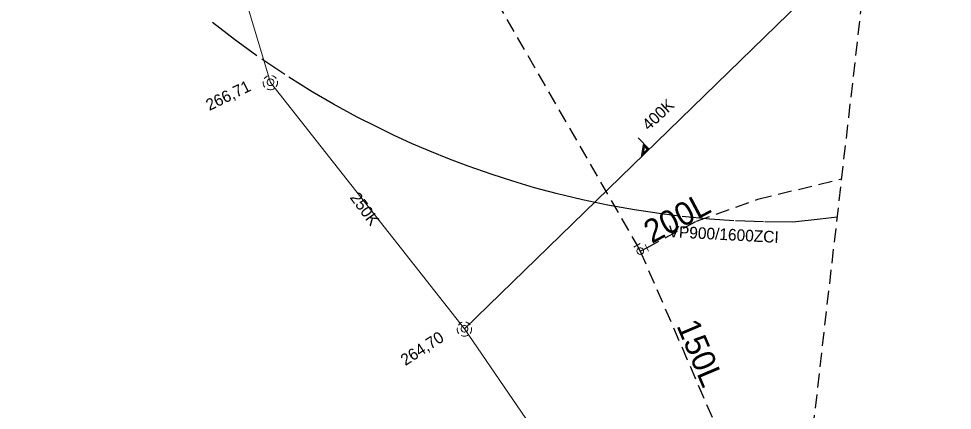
# Model space of a CAD drawing. Extents: x -743212 to -743020, y -1051380 to -1051228.
# Drawn here: x -743084.5 to -743020, y -1051325.4 to -1051298.4 of the extents above; entities that cross this region are included whole.
import ezdxf

# ---------------------------------------------------------------- set-up
doc = ezdxf.new("R2010")
doc.units = 0
doc.header["$LTSCALE"] = 0.32
doc.linetypes.add('LONG_DASHED', pattern=[7.5, 6, -1.5])
doc.linetypes.add('MEDIUM_DASHED', pattern=[4.5, 3, -1.5])
for name, color, linetype, lineweight in [('1', 7, 'MEDIUM_DASHED', 25), ('18', 7, 'Continuous', 13), ('20', 7, 'Continuous', 13), ('8', 7, 'Continuous', 13)]:
    doc.layers.add(name, color=color, linetype=linetype, lineweight=lineweight)

msp = doc.modelspace()

# ---------------------------------------------------------------- linework, layer by layer
at = {"layer": '1'}
msp.add_lwpolyline([(-743194.153, -1051227.724), (-743020.025, -1051242.759), (-743020.023, -1051242.759), (-743020.021, -1051242.76), (-743020.02, -1051242.761), (-743020.018, -1051242.762), (-743020.017, -1051242.764), (-743020.016, -1051242.766), (-743020.016, -1051242.768), (-743020.016, -1051242.77), (-743035.817, -1051380.315), (-743035.817, -1051380.317), (-743035.818, -1051380.318), (-743035.819, -1051380.32), (-743035.82, -1051380.321), (-743035.822, -1051380.322), (-743035.824, -1051380.323), (-743035.826, -1051380.323), (-743035.828, -1051380.323), (-743211.786, -1051358.847)], dxfattribs=at)
at = {"layer": '18'}
for points in [[(-743067.253, -1051302.337), (-743067.324, -1051302.365), (-743067.391, -1051302.404), (-743067.451, -1051302.452), (-743067.502, -1051302.509), (-743067.526, -1051302.543)], [(-743066.712, -1051302.52), (-743066.762, -1051302.462), (-743066.82, -1051302.412), (-743066.885, -1051302.371), (-743066.956, -1051302.342), (-743067.005, -1051302.328)], [(-743067.598, -1051302.729), (-743067.603, -1051302.806), (-743067.598, -1051302.883), (-743067.581, -1051302.958), (-743067.553, -1051303.029), (-743067.512, -1051303.095), (-743067.497, -1051303.117)], [(-743066.717, -1051303.106), (-743066.676, -1051303.041), (-743066.645, -1051302.971), (-743066.625, -1051302.896), (-743066.618, -1051302.82), (-743066.623, -1051302.743), (-743066.629, -1051302.708)], [(-743067.34, -1051303.246), (-743067.27, -1051303.277), (-743067.195, -1051303.296), (-743067.119, -1051303.303), (-743067.042, -1051303.298), (-743066.967, -1051303.281), (-743066.895, -1051303.253), (-743066.835, -1051303.218)], [(-743041.712, -1051306.626), (-743040.948, -1051307.412), (-743041.5, -1051307.948), (-743041.351, -1051306.997)], [(-743041.305, -1051307.117), (-743041.015, -1051307.415), (-743041.421, -1051307.81), (-743041.305, -1051307.116)], [(-743041.28, -1051307.21), (-743041.077, -1051307.418), (-743041.344, -1051307.678), (-743041.279, -1051307.209)], [(-743054.197, -1051319.729), (-743054.203, -1051319.806), (-743054.198, -1051319.883), (-743054.181, -1051319.958), (-743054.152, -1051320.029), (-743054.112, -1051320.095), (-743054.096, -1051320.117)], [(-743053.852, -1051319.337), (-743053.923, -1051319.365), (-743053.99, -1051319.404), (-743054.05, -1051319.452), (-743054.101, -1051319.509), (-743054.125, -1051319.543)], [(-743053.311, -1051319.52), (-743053.361, -1051319.462), (-743053.419, -1051319.412), (-743053.484, -1051319.371), (-743053.555, -1051319.342), (-743053.604, -1051319.328)], [(-743053.316, -1051320.106), (-743053.275, -1051320.041), (-743053.244, -1051319.971), (-743053.225, -1051319.896), (-743053.217, -1051319.82), (-743053.222, -1051319.743), (-743053.228, -1051319.708)], [(-743053.939, -1051320.246), (-743053.869, -1051320.277), (-743053.794, -1051320.296), (-743053.718, -1051320.303), (-743053.641, -1051320.298), (-743053.566, -1051320.281), (-743053.494, -1051320.253), (-743053.434, -1051320.218)]]:
    msp.add_lwpolyline(points, dxfattribs=at)
for points in [[(-743066.869, -1051302.789), (-743066.875, -1051302.737), (-743066.892, -1051302.687), (-743066.921, -1051302.643), (-743066.959, -1051302.606), (-743067.004, -1051302.579), (-743067.054, -1051302.563), (-743067.106, -1051302.558), (-743067.157, -1051302.565), (-743067.206, -1051302.584), (-743067.25, -1051302.614), (-743067.286, -1051302.653), (-743067.312, -1051302.698), (-743067.326, -1051302.749), (-743067.33, -1051302.801), (-743067.321, -1051302.853), (-743067.301, -1051302.901), (-743067.271, -1051302.944), (-743067.231, -1051302.979), (-743067.184, -1051303.003), (-743067.134, -1051303.017), (-743067.081, -1051303.019), (-743067.03, -1051303.009), (-743066.982, -1051302.987), (-743066.94, -1051302.955), (-743066.907, -1051302.915), (-743066.883, -1051302.868), (-743066.87, -1051302.817)], [(-743053.468, -1051319.789), (-743053.474, -1051319.737), (-743053.492, -1051319.687), (-743053.52, -1051319.643), (-743053.558, -1051319.606), (-743053.603, -1051319.579), (-743053.653, -1051319.563), (-743053.705, -1051319.558), (-743053.757, -1051319.565), (-743053.806, -1051319.584), (-743053.85, -1051319.614), (-743053.885, -1051319.653), (-743053.911, -1051319.698), (-743053.926, -1051319.749), (-743053.929, -1051319.801), (-743053.921, -1051319.853), (-743053.9, -1051319.901), (-743053.87, -1051319.944), (-743053.83, -1051319.979), (-743053.784, -1051320.003), (-743053.733, -1051320.017), (-743053.681, -1051320.019), (-743053.629, -1051320.009), (-743053.581, -1051319.987), (-743053.539, -1051319.955), (-743053.506, -1051319.915), (-743053.482, -1051319.868), (-743053.47, -1051319.817)]]:
    msp.add_lwpolyline(points, close=True, dxfattribs=at)
at = {"layer": '20'}
for p, q in [((-743078.3, -1051265.399), (-743067.1, -1051302.8)), ((-743078.3, -1051265.399), (-743067.1, -1051302.8)), ((-743030.49, -1051297.252), (-743053.699, -1051319.8)), ((-743030.49, -1051297.252), (-743053.699, -1051319.8)), ((-743067.1, -1051302.8), (-743053.699, -1051319.8)), ((-743067.1, -1051302.8), (-743053.699, -1051319.8)), ((-743053.699, -1051319.8), (-743032.423, -1051350.772)), ((-743053.699, -1051319.8), (-743032.423, -1051350.772))]:
    msp.add_line(p, q, dxfattribs=at)
at = {"layer": '20', "linetype": 'LONG_DASHED', "lineweight": 25}
msp.add_lwpolyline([(-743027.979, -1051312.087), (-743029.131, -1051312.22), (-743031.032, -1051312.425), (-743033.063, -1051312.414), (-743035.112, -1051312.336), (-743036.755, -1051312.226), (-743038.886, -1051312.019), (-743040.265, -1051311.847), (-743041.959, -1051311.592), (-743043.811, -1051311.26), (-743045.547, -1051310.896), (-743047.364, -1051310.461), (-743048.863, -1051310.059), (-743050.376, -1051309.612), (-743051.855, -1051309.136), (-743053.439, -1051308.581), (-743054.745, -1051308.087), (-743056.085, -1051307.546), (-743057.354, -1051307), (-743058.604, -1051306.43), (-743059.764, -1051305.871), (-743061.109, -1051305.186), (-743062.739, -1051304.301), (-743064.21, -1051303.447), (-743066.115, -1051302.261), (-743068.031, -1051300.971), (-743069.586, -1051299.847), (-743071.454, -1051298.396)], dxfattribs=at)
msp.add_lwpolyline([(-743027.979, -1051312.087), (-743029.131, -1051312.22), (-743031.032, -1051312.425), (-743033.063, -1051312.414), (-743035.112, -1051312.336), (-743036.755, -1051312.226), (-743038.886, -1051312.019), (-743040.265, -1051311.847), (-743041.959, -1051311.592), (-743043.811, -1051311.26), (-743045.547, -1051310.896), (-743047.364, -1051310.461), (-743048.863, -1051310.059), (-743050.376, -1051309.612), (-743051.855, -1051309.136), (-743053.439, -1051308.581), (-743054.745, -1051308.087), (-743056.085, -1051307.546), (-743057.354, -1051307), (-743058.604, -1051306.43), (-743059.764, -1051305.871), (-743061.109, -1051305.186), (-743062.739, -1051304.301), (-743064.21, -1051303.447), (-743066.115, -1051302.261), (-743068.031, -1051300.971), (-743069.586, -1051299.847), (-743071.454, -1051298.396)], dxfattribs=at)
at = {"layer": '8'}
for p, q in [((-743041.563, -1051313.912), (-743042.013, -1051314.166)), ((-743041.238, -1051313.968), (-743040.999, -1051314.427))]:
    msp.add_line(p, q, dxfattribs=at)
at = {"layer": '8', "linetype": 'MEDIUM_DASHED', "lineweight": 25}
for p, q in [((-743041.789, -1051314.04), (-743041.565, -1051314.439)), ((-743041.565, -1051314.439), (-743041.12, -1051314.2)), ((-743041.565, -1051314.439), (-743035.204, -1051329.117))]:
    msp.add_line(p, q, dxfattribs=at)
for points in [[(-743072.836, -1051238.199), (-743072.636, -1051242.843), (-743068.943, -1051266.389), (-743067.317, -1051269.764), (-743041.789, -1051314.04)], [(-743041.12, -1051314.2), (-743037.686, -1051312.358), (-743033.443, -1051310.858), (-743027.675, -1051309.442)]]:
    msp.add_lwpolyline(points, dxfattribs=at)
at = {"layer": '8'}
msp.add_lwpolyline([(-743041.333, -1051314.428), (-743041.34, -1051314.376), (-743041.357, -1051314.326), (-743041.386, -1051314.282), (-743041.424, -1051314.245), (-743041.468, -1051314.218), (-743041.519, -1051314.202), (-743041.571, -1051314.197), (-743041.622, -1051314.204), (-743041.671, -1051314.223), (-743041.715, -1051314.253), (-743041.75, -1051314.292), (-743041.777, -1051314.337), (-743041.791, -1051314.388), (-743041.794, -1051314.44), (-743041.786, -1051314.492), (-743041.766, -1051314.54), (-743041.735, -1051314.583), (-743041.696, -1051314.618), (-743041.649, -1051314.642), (-743041.598, -1051314.656), (-743041.546, -1051314.658), (-743041.495, -1051314.648), (-743041.446, -1051314.626), (-743041.404, -1051314.594), (-743041.372, -1051314.554), (-743041.348, -1051314.507), (-743041.335, -1051314.456)], close=True, dxfattribs=at)

# ---------------------------------------------------------------- texts
at = {"layer": '1'}
for s, height, rotation, p in [('266,71', 0.8, 26, (-743071.32, -1051304.77)), ('400K', 0.8, 43, (-743040.979, -1051306.163)), ('250K', 0.8, 306, (-743061.646, -1051310.743)), ('200L', 1.6, 28, (-743040.77, -1051313.942)), ('VP900/1600ZCI ', 0.8, 357, (-743039.625, -1051313.47)), ('150L', 1.6, 293, (-743039.082, -1051319.57)), ('264,70', 0.8, 33, (-743057.786, -1051322.368))]:
    msp.add_text(s, height=height, rotation=rotation, dxfattribs=at).set_placement(p)

doc.saveas('drawing.dxf')
